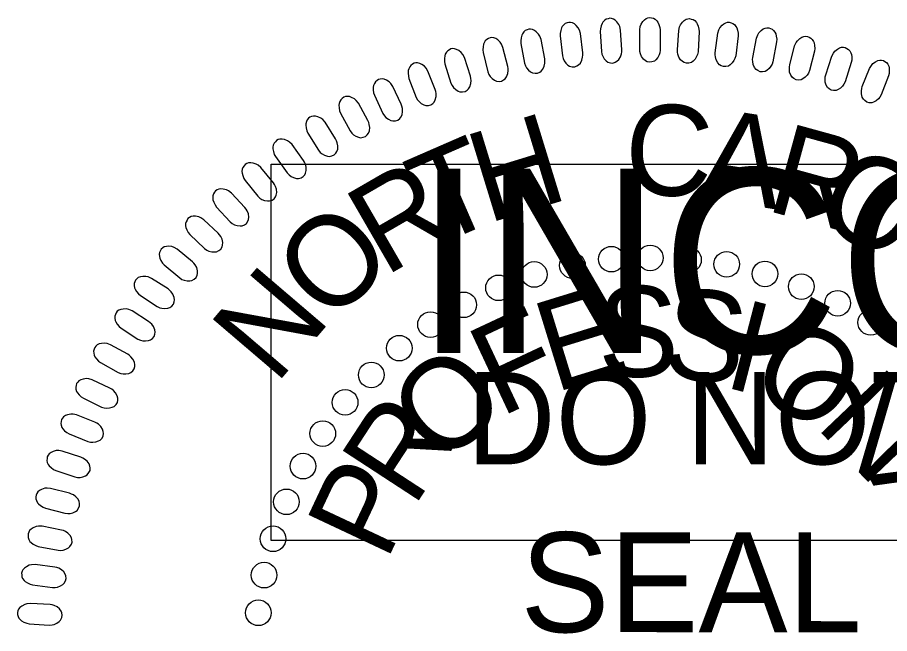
# Model space of a CAD drawing. Extents: x 505602 to 507286, y 483109 to 484209.
# Drawn here: x 507079.7 to 507134.2, y 484096.7 to 484135.2 of the extents above; entities that cross this region are included whole.
import ezdxf

# ---------------------------------------------------------------- set-up
doc = ezdxf.new("R2010")
doc.units = 0
doc.layers.add('Sheet PE Seal Cell', color=7, linetype='Continuous')
doc.layers.add('Sheet Sticker Incomplete CELL', color=7, linetype='Continuous')

msp = doc.modelspace()

# ---------------------------------------------------------------- linework, layer by layer
at = {"layer": 'Sheet PE Seal Cell'}
for points in [[(507118.615, 484133.164), (507118.615, 484134.391), (507118.653, 484134.61), (507118.705, 484134.751), (507118.817, 484134.92), (507118.915, 484135.029), (507119.027, 484135.109), (507119.131, 484135.149), (507119.244, 484135.169), (507119.355, 484135.149), (507119.475, 484135.119), (507119.58, 484135.059), (507119.684, 484134.959), (507119.744, 484134.879), (507119.811, 484134.73), (507119.871, 484134.55), (507119.894, 484134.39), (507119.901, 484133.134), (507119.878, 484132.964), (507119.833, 484132.825), (507119.744, 484132.666), (507119.631, 484132.525), (507119.534, 484132.446), (507119.377, 484132.386), (507119.228, 484132.367), (507119.078, 484132.406), (507118.974, 484132.456), (507118.846, 484132.556), (507118.727, 484132.726), (507118.66, 484132.905), (507118.63, 484133.035)], [(507115.061, 484132.953), (507114.908, 484134.17), (507114.844, 484134.383), (507114.774, 484134.515), (507114.642, 484134.669), (507114.531, 484134.766), (507114.411, 484134.831), (507114.301, 484134.857), (507114.187, 484134.863), (507114.079, 484134.829), (507113.964, 484134.785), (507113.868, 484134.712), (507113.776, 484134.6), (507113.727, 484134.513), (507113.679, 484134.357), (507113.642, 484134.171), (507113.64, 484134.01), (507113.79, 484132.763), (507113.833, 484132.597), (507113.895, 484132.464), (507114.003, 484132.317), (507114.132, 484132.192), (507114.239, 484132.126), (507114.402, 484132.085), (507114.553, 484132.084), (507114.696, 484132.143), (507114.794, 484132.205), (507114.907, 484132.32), (507115.005, 484132.503), (507115.049, 484132.69), (507115.062, 484132.822)], [(507117.5, 484133.155), (507117.423, 484134.38), (507117.372, 484134.596), (507117.311, 484134.732), (507117.188, 484134.895), (507117.085, 484134.998), (507116.968, 484135.071), (507116.861, 484135.104), (507116.747, 484135.117), (507116.637, 484135.09), (507116.52, 484135.053), (507116.419, 484134.987), (507116.321, 484134.88), (507116.266, 484134.797), (507116.208, 484134.643), (507116.159, 484134.46), (507116.147, 484134.3), (507116.218, 484133.045), (507116.251, 484132.878), (507116.305, 484132.741), (507116.404, 484132.587), (507116.525, 484132.455), (507116.626, 484132.381), (507116.787, 484132.331), (507116.938, 484132.321), (507117.085, 484132.37), (507117.186, 484132.427), (507117.306, 484132.534), (507117.415, 484132.71), (507117.471, 484132.894), (507117.493, 484133.025)], [(507120.974, 484133.138), (507121.051, 484134.362), (507121.102, 484134.579), (507121.163, 484134.715), (507121.286, 484134.877), (507121.39, 484134.98), (507121.507, 484135.053), (507121.614, 484135.086), (507121.727, 484135.099), (507121.838, 484135.071), (507121.955, 484135.034), (507122.056, 484134.968), (507122.154, 484134.862), (507122.209, 484134.779), (507122.267, 484134.625), (507122.315, 484134.442), (507122.327, 484134.282), (507122.255, 484133.027), (507122.222, 484132.859), (507122.169, 484132.723), (507122.069, 484132.569), (507121.948, 484132.437), (507121.846, 484132.363), (507121.686, 484132.313), (507121.535, 484132.303), (507121.389, 484132.352), (507121.287, 484132.409), (507121.167, 484132.516), (507121.059, 484132.693), (507121.002, 484132.876), (507120.981, 484133.008)], [(507123.336, 484132.963), (507123.491, 484134.18), (507123.555, 484134.393), (507123.625, 484134.524), (507123.757, 484134.679), (507123.868, 484134.776), (507123.989, 484134.84), (507124.097, 484134.867), (507124.211, 484134.873), (507124.32, 484134.838), (507124.434, 484134.794), (507124.531, 484134.721), (507124.622, 484134.609), (507124.672, 484134.523), (507124.72, 484134.366), (507124.756, 484134.18), (507124.759, 484134.019), (507124.608, 484132.771), (507124.564, 484132.606), (507124.503, 484132.473), (507124.394, 484132.326), (507124.265, 484132.202), (507124.159, 484132.135), (507123.995, 484132.095), (507123.844, 484132.094), (507123.701, 484132.153), (507123.603, 484132.215), (507123.489, 484132.33), (507123.392, 484132.513), (507123.348, 484132.7), (507123.335, 484132.833)], [(507112.68, 484132.585), (507112.451, 484133.789), (507112.373, 484133.998), (507112.296, 484134.126), (507112.153, 484134.271), (507112.038, 484134.36), (507111.913, 484134.418), (507111.803, 484134.438), (507111.688, 484134.437), (507111.582, 484134.396), (507111.47, 484134.344), (507111.378, 484134.266), (507111.294, 484134.148), (507111.25, 484134.058), (507111.213, 484133.899), (507111.187, 484133.712), (507111.195, 484133.551), (507111.423, 484132.315), (507111.476, 484132.152), (507111.546, 484132.023), (507111.665, 484131.884), (507111.801, 484131.767), (507111.911, 484131.707), (507112.077, 484131.678), (507112.227, 484131.687), (507112.367, 484131.754), (507112.46, 484131.822), (507112.566, 484131.944), (507112.652, 484132.132), (507112.685, 484132.321), (507112.689, 484132.454)], [(507125.676, 484132.676), (507125.906, 484133.881), (507125.984, 484134.09), (507126.062, 484134.217), (507126.204, 484134.362), (507126.319, 484134.452), (507126.444, 484134.509), (507126.555, 484134.529), (507126.669, 484134.528), (507126.775, 484134.487), (507126.887, 484134.435), (507126.979, 484134.356), (507127.063, 484134.239), (507127.106, 484134.149), (507127.144, 484133.99), (507127.17, 484133.802), (507127.162, 484133.641), (507126.933, 484132.405), (507126.879, 484132.243), (507126.809, 484132.115), (507126.691, 484131.974), (507126.554, 484131.858), (507126.444, 484131.798), (507126.279, 484131.769), (507126.128, 484131.778), (507125.989, 484131.845), (507125.896, 484131.913), (507125.789, 484132.035), (507125.704, 484132.224), (507125.671, 484132.413), (507125.666, 484132.546)], [(507110.375, 484132.112), (507110.07, 484133.301), (507109.98, 484133.504), (507109.894, 484133.627), (507109.743, 484133.763), (507109.622, 484133.844), (507109.494, 484133.894), (507109.382, 484133.907), (507109.269, 484133.898), (507109.165, 484133.852), (507109.057, 484133.792), (507108.97, 484133.709), (507108.893, 484133.586), (507108.855, 484133.494), (507108.827, 484133.332), (507108.814, 484133.144), (507108.832, 484132.984), (507109.137, 484131.764), (507109.2, 484131.606), (507109.279, 484131.482), (507109.405, 484131.349), (507109.549, 484131.242), (507109.662, 484131.189), (507109.83, 484131.169), (507109.979, 484131.187), (507110.114, 484131.263), (507110.203, 484131.337), (507110.301, 484131.466), (507110.375, 484131.66), (507110.396, 484131.85), (507110.392, 484131.983)], [(507127.981, 484132.202), (507128.286, 484133.39), (507128.377, 484133.593), (507128.463, 484133.716), (507128.614, 484133.853), (507128.735, 484133.934), (507128.863, 484133.984), (507128.975, 484133.996), (507129.089, 484133.988), (507129.192, 484133.941), (507129.3, 484133.882), (507129.387, 484133.798), (507129.463, 484133.675), (507129.501, 484133.583), (507129.529, 484133.421), (507129.543, 484133.232), (507129.525, 484133.072), (507129.219, 484131.853), (507129.154, 484131.695), (507129.076, 484131.571), (507128.95, 484131.439), (507128.806, 484131.331), (507128.693, 484131.278), (507128.526, 484131.259), (507128.376, 484131.277), (507128.241, 484131.353), (507128.152, 484131.427), (507128.054, 484131.556), (507127.98, 484131.75), (507127.96, 484131.94), (507127.963, 484132.073)], [(507108.041, 484131.492), (507107.662, 484132.659), (507107.56, 484132.856), (507107.467, 484132.972), (507107.308, 484133.099), (507107.181, 484133.174), (507107.05, 484133.215), (507106.938, 484133.221), (507106.825, 484133.205), (507106.724, 484133.152), (507106.621, 484133.086), (507106.539, 484132.997), (507106.47, 484132.87), (507106.438, 484132.775), (507106.42, 484132.612), (507106.419, 484132.423), (507106.447, 484132.264), (507106.827, 484131.066), (507106.901, 484130.912), (507106.987, 484130.794), (507107.121, 484130.669), (507107.271, 484130.571), (507107.388, 484130.525), (507107.556, 484130.517), (507107.704, 484130.544), (507107.834, 484130.628), (507107.919, 484130.708), (507108.009, 484130.842), (507108.07, 484131.04), (507108.079, 484131.231), (507108.067, 484131.364)], [(507130.231, 484131.58), (507130.61, 484132.747), (507130.714, 484132.944), (507130.807, 484133.06), (507130.966, 484133.187), (507131.092, 484133.261), (507131.223, 484133.303), (507131.335, 484133.308), (507131.448, 484133.293), (507131.549, 484133.239), (507131.653, 484133.173), (507131.735, 484133.084), (507131.803, 484132.957), (507131.835, 484132.863), (507131.853, 484132.699), (507131.854, 484132.51), (507131.826, 484132.351), (507131.444, 484131.154), (507131.371, 484131), (507131.285, 484130.881), (507131.15, 484130.757), (507131, 484130.659), (507130.883, 484130.613), (507130.715, 484130.605), (507130.567, 484130.633), (507130.437, 484130.716), (507130.353, 484130.796), (507130.263, 484130.93), (507130.202, 484131.128), (507130.193, 484131.32), (507130.205, 484131.453)], [(507132.514, 484130.845), (507132.966, 484131.986), (507133.082, 484132.176), (507133.182, 484132.287), (507133.349, 484132.403), (507133.48, 484132.469), (507133.613, 484132.502), (507133.725, 484132.5), (507133.837, 484132.478), (507133.933, 484132.418), (507134.034, 484132.346), (507134.109, 484132.252), (507134.17, 484132.12), (507134.196, 484132.024), (507134.203, 484131.861), (507134.193, 484131.672), (507134.155, 484131.515), (507133.699, 484130.344), (507133.615, 484130.195), (507133.522, 484130.081), (507133.38, 484129.966), (507133.224, 484129.877), (507133.105, 484129.839), (507132.936, 484129.842), (507132.79, 484129.878), (507132.666, 484129.97), (507132.587, 484130.055), (507132.505, 484130.195), (507132.457, 484130.397), (507132.46, 484130.588), (507132.481, 484130.72)], [(507105.84, 484130.675), (507105.389, 484131.816), (507105.273, 484132.006), (507105.174, 484132.117), (507105.007, 484132.234), (507104.876, 484132.3), (507104.743, 484132.333), (507104.631, 484132.331), (507104.519, 484132.308), (507104.422, 484132.248), (507104.322, 484132.177), (507104.247, 484132.083), (507104.186, 484131.952), (507104.16, 484131.855), (507104.152, 484131.691), (507104.163, 484131.503), (507104.2, 484131.346), (507104.656, 484130.175), (507104.739, 484130.026), (507104.832, 484129.912), (507104.974, 484129.796), (507105.13, 484129.708), (507105.249, 484129.669), (507105.418, 484129.671), (507105.564, 484129.708), (507105.688, 484129.801), (507105.767, 484129.885), (507105.849, 484130.025), (507105.898, 484130.226), (507105.894, 484130.418), (507105.874, 484130.549)], [(507103.723, 484129.743), (507103.201, 484130.853), (507103.074, 484131.035), (507102.967, 484131.139), (507102.794, 484131.246), (507102.659, 484131.303), (507102.523, 484131.327), (507102.412, 484131.319), (507102.302, 484131.29), (507102.209, 484131.224), (507102.113, 484131.146), (507102.044, 484131.047), (507101.992, 484130.912), (507101.972, 484130.815), (507101.974, 484130.651), (507101.997, 484130.463), (507102.044, 484130.309), (507102.572, 484129.169), (507102.665, 484129.024), (507102.765, 484128.917), (507102.914, 484128.812), (507103.075, 484128.732), (507103.196, 484128.702), (507103.364, 484128.715), (507103.508, 484128.76), (507103.626, 484128.86), (507103.7, 484128.949), (507103.772, 484129.093), (507103.808, 484129.298), (507103.793, 484129.489), (507103.765, 484129.619)], [(507101.64, 484128.728), (507101.049, 484129.804), (507100.911, 484129.979), (507100.798, 484130.075), (507100.618, 484130.17), (507100.48, 484130.22), (507100.343, 484130.236), (507100.233, 484130.22), (507100.124, 484130.183), (507100.036, 484130.112), (507099.945, 484130.028), (507099.882, 484129.926), (507099.839, 484129.788), (507099.825, 484129.689), (507099.837, 484129.525), (507099.872, 484129.339), (507099.929, 484129.188), (507100.528, 484128.083), (507100.628, 484127.946), (507100.735, 484127.845), (507100.89, 484127.749), (507101.056, 484127.68), (507101.18, 484127.657), (507101.346, 484127.68), (507101.486, 484127.734), (507101.599, 484127.841), (507101.666, 484127.935), (507101.73, 484128.084), (507101.753, 484128.29), (507101.726, 484128.48), (507101.689, 484128.608)], [(507099.622, 484127.586), (507098.965, 484128.622), (507098.816, 484128.788), (507098.698, 484128.878), (507098.512, 484128.962), (507098.371, 484129.002), (507098.234, 484129.009), (507098.124, 484128.987), (507098.019, 484128.943), (507097.934, 484128.867), (507097.85, 484128.777), (507097.793, 484128.671), (507097.758, 484128.531), (507097.751, 484128.431), (507097.774, 484128.268), (507097.82, 484128.085), (507097.886, 484127.938), (507098.553, 484126.873), (507098.662, 484126.742), (507098.775, 484126.648), (507098.937, 484126.561), (507099.106, 484126.503), (507099.23, 484126.488), (507099.395, 484126.522), (507099.532, 484126.585), (507099.637, 484126.698), (507099.699, 484126.797), (507099.753, 484126.949), (507099.763, 484127.156), (507099.723, 484127.344), (507099.679, 484127.469)], [(507097.622, 484126.232), (507096.901, 484127.225), (507096.742, 484127.38), (507096.618, 484127.463), (507096.427, 484127.534), (507096.284, 484127.566), (507096.147, 484127.564), (507096.038, 484127.535), (507095.936, 484127.485), (507095.857, 484127.403), (507095.778, 484127.309), (507095.728, 484127.199), (507095.702, 484127.057), (507095.7, 484126.957), (507095.734, 484126.796), (507095.791, 484126.616), (507095.867, 484126.474), (507096.599, 484125.453), (507096.717, 484125.329), (507096.835, 484125.241), (507097.001, 484125.165), (507097.174, 484125.118), (507097.3, 484125.11), (507097.462, 484125.155), (507097.594, 484125.226), (507097.692, 484125.346), (507097.747, 484125.448), (507097.792, 484125.604), (507097.789, 484125.811), (507097.738, 484125.996), (507097.686, 484126.119)], [(507095.741, 484124.843), (507094.959, 484125.789), (507094.791, 484125.933), (507094.662, 484126.008), (507094.468, 484126.067), (507094.323, 484126.09), (507094.185, 484126.08), (507094.08, 484126.044), (507093.98, 484125.987), (507093.906, 484125.901), (507093.834, 484125.801), (507093.79, 484125.689), (507093.774, 484125.545), (507093.778, 484125.446), (507093.822, 484125.287), (507093.89, 484125.111), (507093.975, 484124.973), (507094.769, 484124), (507094.895, 484123.884), (507095.018, 484123.805), (507095.189, 484123.739), (507095.364, 484123.703), (507095.49, 484123.704), (507095.649, 484123.758), (507095.777, 484123.838), (507095.867, 484123.964), (507095.916, 484124.068), (507095.95, 484124.226), (507095.934, 484124.433), (507095.872, 484124.614), (507095.812, 484124.734)], [(507093.954, 484123.304), (507093.114, 484124.199), (507092.937, 484124.333), (507092.803, 484124.4), (507092.605, 484124.446), (507092.46, 484124.46), (507092.323, 484124.441), (507092.219, 484124.398), (507092.124, 484124.336), (507092.056, 484124.245), (507091.989, 484124.141), (507091.954, 484124.026), (507091.946, 484123.882), (507091.956, 484123.783), (507092.01, 484123.627), (507092.089, 484123.456), (507092.181, 484123.324), (507093.037, 484122.402), (507093.169, 484122.294), (507093.297, 484122.224), (507093.472, 484122.168), (507093.65, 484122.143), (507093.775, 484122.151), (507093.93, 484122.215), (507094.053, 484122.303), (507094.134, 484122.435), (507094.177, 484122.542), (507094.201, 484122.702), (507094.173, 484122.907), (507094.098, 484123.084), (507094.032, 484123.199)], [(507092.291, 484121.695), (507091.398, 484122.535), (507091.212, 484122.658), (507091.074, 484122.715), (507090.874, 484122.75), (507090.728, 484122.754), (507090.592, 484122.727), (507090.492, 484122.678), (507090.401, 484122.61), (507090.339, 484122.515), (507090.278, 484122.407), (507090.25, 484122.29), (507090.251, 484122.145), (507090.268, 484122.047), (507090.331, 484121.895), (507090.421, 484121.729), (507090.522, 484121.603), (507091.433, 484120.737), (507091.571, 484120.638), (507091.704, 484120.574), (507091.882, 484120.531), (507092.06, 484120.517), (507092.185, 484120.533), (507092.336, 484120.606), (507092.453, 484120.702), (507092.526, 484120.838), (507092.561, 484120.948), (507092.576, 484121.109), (507092.534, 484121.313), (507092.45, 484121.485), (507092.376, 484121.595)], [(507090.678, 484119.908), (507089.733, 484120.69), (507089.54, 484120.801), (507089.399, 484120.85), (507089.197, 484120.872), (507089.051, 484120.867), (507088.918, 484120.831), (507088.821, 484120.776), (507088.734, 484120.702), (507088.677, 484120.603), (507088.625, 484120.492), (507088.603, 484120.374), (507088.614, 484120.229), (507088.637, 484120.132), (507088.709, 484119.985), (507088.81, 484119.824), (507088.918, 484119.705), (507089.881, 484118.898), (507090.026, 484118.807), (507090.162, 484118.753), (507090.343, 484118.72), (507090.521, 484118.718), (507090.645, 484118.742), (507090.791, 484118.825), (507090.901, 484118.927), (507090.966, 484119.068), (507090.995, 484119.18), (507090.999, 484119.342), (507090.945, 484119.541), (507090.849, 484119.708), (507090.768, 484119.814)], [(507089.153, 484118.206), (507088.123, 484118.871), (507087.918, 484118.959), (507087.773, 484118.991), (507087.57, 484118.989), (507087.425, 484118.967), (507087.297, 484118.916), (507087.207, 484118.85), (507087.129, 484118.766), (507087.085, 484118.661), (507087.046, 484118.544), (507087.038, 484118.424), (507087.066, 484118.282), (507087.1, 484118.189), (507087.189, 484118.051), (507087.308, 484117.903), (507087.429, 484117.798), (507088.481, 484117.11), (507088.635, 484117.036), (507088.777, 484116.998), (507088.96, 484116.987), (507089.138, 484117.005), (507089.258, 484117.044), (507089.393, 484117.143), (507089.491, 484117.258), (507089.538, 484117.405), (507089.553, 484117.52), (507089.539, 484117.681), (507089.461, 484117.873), (507089.347, 484118.027), (507089.254, 484118.123)], [(507087.939, 484116.183), (507086.904, 484116.84), (507086.699, 484116.926), (507086.553, 484116.957), (507086.349, 484116.954), (507086.204, 484116.93), (507086.077, 484116.879), (507085.987, 484116.812), (507085.91, 484116.727), (507085.867, 484116.622), (507085.828, 484116.505), (507085.822, 484116.385), (507085.851, 484116.243), (507085.886, 484116.15), (507085.976, 484116.012), (507086.095, 484115.866), (507086.218, 484115.762), (507087.275, 484115.082), (507087.43, 484115.01), (507087.572, 484114.972), (507087.755, 484114.963), (507087.933, 484114.983), (507088.052, 484115.021), (507088.187, 484115.122), (507088.284, 484115.238), (507088.33, 484115.385), (507088.344, 484115.5), (507088.328, 484115.661), (507088.25, 484115.853), (507088.134, 484116.006), (507088.04, 484116.101)], [(507086.636, 484114.133), (507085.561, 484114.725), (507085.351, 484114.798), (507085.203, 484114.82), (507085, 484114.803), (507084.857, 484114.771), (507084.733, 484114.711), (507084.648, 484114.639), (507084.576, 484114.55), (507084.54, 484114.442), (507084.509, 484114.323), (507084.51, 484114.202), (507084.548, 484114.063), (507084.589, 484113.972), (507084.687, 484113.841), (507084.816, 484113.702), (507084.945, 484113.605), (507086.042, 484112.993), (507086.201, 484112.931), (507086.345, 484112.903), (507086.528, 484112.905), (507086.705, 484112.935), (507086.822, 484112.982), (507086.95, 484113.091), (507087.039, 484113.213), (507087.076, 484113.362), (507087.083, 484113.478), (507087.057, 484113.638), (507086.966, 484113.824), (507086.841, 484113.969), (507086.742, 484114.058)], [(507085.527, 484112.01), (507084.417, 484112.532), (507084.203, 484112.592), (507084.054, 484112.605), (507083.853, 484112.575), (507083.712, 484112.534), (507083.592, 484112.467), (507083.511, 484112.389), (507083.446, 484112.296), (507083.416, 484112.186), (507083.392, 484112.065), (507083.401, 484111.945), (507083.447, 484111.808), (507083.494, 484111.72), (507083.601, 484111.595), (507083.738, 484111.464), (507083.872, 484111.376), (507085.007, 484110.834), (507085.169, 484110.782), (507085.314, 484110.764), (507085.497, 484110.776), (507085.671, 484110.819), (507085.784, 484110.872), (507085.906, 484110.989), (507085.988, 484111.116), (507086.015, 484111.268), (507086.014, 484111.384), (507085.978, 484111.541), (507085.876, 484111.722), (507085.742, 484111.859), (507085.637, 484111.941)], [(507084.587, 484109.891), (507083.447, 484110.343), (507083.229, 484110.389), (507083.08, 484110.392), (507082.881, 484110.35), (507082.743, 484110.3), (507082.628, 484110.225), (507082.553, 484110.142), (507082.492, 484110.045), (507082.47, 484109.934), (507082.454, 484109.812), (507082.47, 484109.693), (507082.525, 484109.559), (507082.577, 484109.473), (507082.691, 484109.356), (507082.836, 484109.235), (507082.976, 484109.155), (507084.141, 484108.685), (507084.307, 484108.643), (507084.454, 484108.634), (507084.635, 484108.658), (507084.806, 484108.711), (507084.916, 484108.772), (507085.03, 484108.896), (507085.103, 484109.027), (507085.121, 484109.18), (507085.113, 484109.297), (507085.068, 484109.452), (507084.954, 484109.625), (507084.812, 484109.754), (507084.702, 484109.829)], [(507083.712, 484107.702), (507082.545, 484108.081), (507082.325, 484108.113), (507082.176, 484108.107), (507081.98, 484108.053), (507081.845, 484107.994), (507081.735, 484107.912), (507081.665, 484107.826), (507081.611, 484107.725), (507081.596, 484107.612), (507081.587, 484107.489), (507081.611, 484107.371), (507081.674, 484107.241), (507081.732, 484107.159), (507081.853, 484107.048), (507082.005, 484106.937), (507082.15, 484106.866), (507083.342, 484106.469), (507083.51, 484106.439), (507083.657, 484106.438), (507083.837, 484106.474), (507084.004, 484106.538), (507084.111, 484106.605), (507084.216, 484106.736), (507084.281, 484106.872), (507084.289, 484107.027), (507084.274, 484107.141), (507084.219, 484107.293), (507084.094, 484107.459), (507083.944, 484107.579), (507083.83, 484107.648)], [(507083.007, 484105.446), (507081.819, 484105.751), (507081.598, 484105.77), (507081.449, 484105.755), (507081.257, 484105.688), (507081.126, 484105.621), (507081.021, 484105.533), (507080.957, 484105.441), (507080.909, 484105.337), (507080.9, 484105.224), (507080.9, 484105.1), (507080.931, 484104.984), (507081.002, 484104.858), (507081.064, 484104.78), (507081.193, 484104.677), (507081.352, 484104.576), (507081.501, 484104.514), (507082.716, 484104.193), (507082.886, 484104.173), (507083.032, 484104.182), (507083.209, 484104.229), (507083.372, 484104.302), (507083.474, 484104.377), (507083.571, 484104.514), (507083.627, 484104.654), (507083.626, 484104.808), (507083.603, 484104.922), (507083.539, 484105.071), (507083.404, 484105.228), (507083.247, 484105.338), (507083.128, 484105.399)], [(507082.496, 484103.15), (507081.291, 484103.381), (507081.069, 484103.385), (507080.921, 484103.361), (507080.734, 484103.282), (507080.608, 484103.207), (507080.508, 484103.112), (507080.45, 484103.017), (507080.409, 484102.91), (507080.408, 484102.797), (507080.415, 484102.673), (507080.453, 484102.559), (507080.532, 484102.438), (507080.599, 484102.364), (507080.733, 484102.27), (507080.899, 484102.177), (507081.051, 484102.125), (507082.284, 484101.882), (507082.455, 484101.872), (507082.601, 484101.891), (507082.774, 484101.948), (507082.932, 484102.032), (507083.029, 484102.113), (507083.117, 484102.256), (507083.165, 484102.399), (507083.154, 484102.554), (507083.124, 484102.665), (507083.05, 484102.809), (507082.906, 484102.958), (507082.742, 484103.058), (507082.62, 484103.112)], [(507082.076, 484100.836), (507080.859, 484100.99), (507080.636, 484100.981), (507080.491, 484100.947), (507080.309, 484100.857), (507080.187, 484100.774), (507080.094, 484100.673), (507080.042, 484100.574), (507080.008, 484100.465), (507080.014, 484100.352), (507080.028, 484100.229), (507080.074, 484100.118), (507080.161, 484100.002), (507080.232, 484099.932), (507080.372, 484099.846), (507080.542, 484099.765), (507080.698, 484099.722), (507081.944, 484099.557), (507082.115, 484099.558), (507082.259, 484099.585), (507082.428, 484099.654), (507082.581, 484099.748), (507082.672, 484099.835), (507082.752, 484099.982), (507082.79, 484100.128), (507082.769, 484100.281), (507082.733, 484100.392), (507082.65, 484100.53), (507082.497, 484100.67), (507082.327, 484100.759), (507082.202, 484100.805)], [(507081.789, 484098.492), (507080.565, 484098.57), (507080.343, 484098.546), (507080.2, 484098.503), (507080.024, 484098.402), (507079.908, 484098.312), (507079.822, 484098.205), (507079.776, 484098.103), (507079.749, 484097.992), (507079.762, 484097.879), (507079.784, 484097.757), (507079.837, 484097.65), (507079.93, 484097.539), (507080.006, 484097.474), (507080.151, 484097.397), (507080.326, 484097.326), (507080.484, 484097.294), (507081.738, 484097.207), (507081.908, 484097.219), (507082.05, 484097.255), (507082.215, 484097.335), (507082.362, 484097.437), (507082.448, 484097.529), (507082.517, 484097.682), (507082.546, 484097.83), (507082.516, 484097.982), (507082.473, 484098.09), (507082.382, 484098.223), (507082.22, 484098.352), (507082.045, 484098.432), (507081.917, 484098.469)]]:
    msp.add_lwpolyline(points, close=True, dxfattribs=at)
for centre in [(507114.414, 484119.671), (507116.843, 484120.069), (507119.272, 484120.147), (507121.661, 484120.027), (507124.049, 484119.748), (507112.025, 484119.114), (507126.438, 484119.149), (507109.796, 484118.278), (507128.707, 484118.352), (507107.621, 484117.217), (507130.976, 484117.315), (507105.55, 484115.983), (507133.046, 484116.119), (507103.599, 484114.51), (507101.847, 484112.837), (507100.214, 484111.125), (507098.82, 484109.173), (507097.585, 484107.142), (507096.549, 484104.911), (507095.712, 484102.601), (507095.154, 484100.331), (507094.795, 484097.98)]:
    msp.add_circle(centre, 0.801, dxfattribs=at)
at = {"layer": 'Sheet Sticker Incomplete CELL'}
msp.add_lwpolyline([(507095.597, 484102.505), (507095.597, 484126.005), (507242.597, 484126.005), (507242.597, 484102.505)], close=True, dxfattribs=at)

# ---------------------------------------------------------------- texts
at = {"layer": 'Sheet PE Seal Cell'}
for s, height, rotation, p in [('C', 5.669, 357.5877, (507117.59, 484124.159)), ('A', 5.669, 351.0983, (507122.165, 484123.951)), ('H', 5.669, 17.0557, (507109.084, 484122.275)), ('R', 5.669, 344.609, (507126.371, 484123.156)), ('T', 5.669, 23.5451, (507105.906, 484120.865)), ('O', 5.669, 331.6302, (507129.326, 484122.502)), ('R', 5.669, 30.0345, (507102.685, 484118.947)), ('O', 5.669, 43.0132, (507099.209, 484115.918)), ('N', 5.669, 49.5025, (507095.863, 484112.163)), ('E', 5.669, 17.1686, (507113.281, 484111.706)), ('S', 5.669, 1.289, (507116.048, 484112.666)), ('S', 5.669, 353.3492, (507119.909, 484112.767)), ('I', 5.669, 345.4094, (507123.709, 484112.136)), ('F', 5.669, 25.1084, (507109.891, 484110.168)), ('O', 5.669, 329.5298, (507125.213, 484111.964)), ('O', 5.669, 40.988, (507106.194, 484107.029)), ('N', 5.669, 313.6502, (507129.525, 484109.659)), ('R', 5.669, 56.8676, (507104.48, 484104.483)), ('P', 5.669, 64.8074, (507102.793, 484101.121)), ('A', 5.669, 297.7707, (507132.862, 484106.579)), ('SEAL', 6.2363, 359.9814, (507111.164, 484096.772))]:
    msp.add_text(s, height=height, rotation=rotation, dxfattribs=at).set_placement(p)
at = {"layer": 'Sheet Sticker Incomplete CELL'}
for s, height, p in [('INCOMPLETE PLANS', 11.52, (507104.547, 484114.205)), ('DO NOT USE FOR R/W ACQUISITION', 5.76, (507107.797, 484107.255))]:
    msp.add_text(s, height=height, dxfattribs=at).set_placement(p)

doc.saveas('drawing.dxf')
